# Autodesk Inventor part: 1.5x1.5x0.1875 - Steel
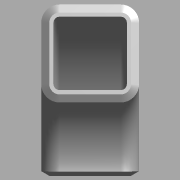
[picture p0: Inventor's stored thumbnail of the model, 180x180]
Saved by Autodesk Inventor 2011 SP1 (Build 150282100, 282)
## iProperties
Created: 2011-03
Part Number: 1.5x1.5x0.1875 - Steel
Material: Default
Document SubType Name: Modeling
Designer: bamfomg
Density: 1 g/cm^3
Author: bamfomg
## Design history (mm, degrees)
derived "Square Tube Corners.ipt" dims "d2" = 19.05, "d3" = 19.05, "d6" = 4.7625, "d7" = 4.7625, "d8" = 4.7625, "d12" = 90 deg, "d16" = 3.175, "d18" = 30 deg, "ID_Rad" = 2.38125, "OD_Rad" = 7.14375, "Side_One" = 38.1, "Side_Two" = 38.1, "Thickness" = 4.7625, "Bend_IDRad" = 28.575, "Bevel_Angl" = 30 deg, "Bevel_Dist" = 3.175
body "Solid1"
feature "Solid1::Square Tube Corners.ipt" dims "d2" = 19.05, "d3" = 19.05, "d6" = 4.7625, "d7" = 4.7625, "d8" = 4.7625, "d12" = 90 deg, "d16" = 3.175, "d18" = 30 deg, "ID_Rad" = 2.38125, "OD_Rad" = 7.14375, "Side_One" = 38.1, "Side_Two" = 38.1, "Thickness" = 4.7625, "Bend_IDRad" = 28.575, "Bevel_Angl" = 30 deg, "Bevel_Dist" = 3.175, "ScaleForDerivedMember" = 10
tag "TaggingFeature1"
